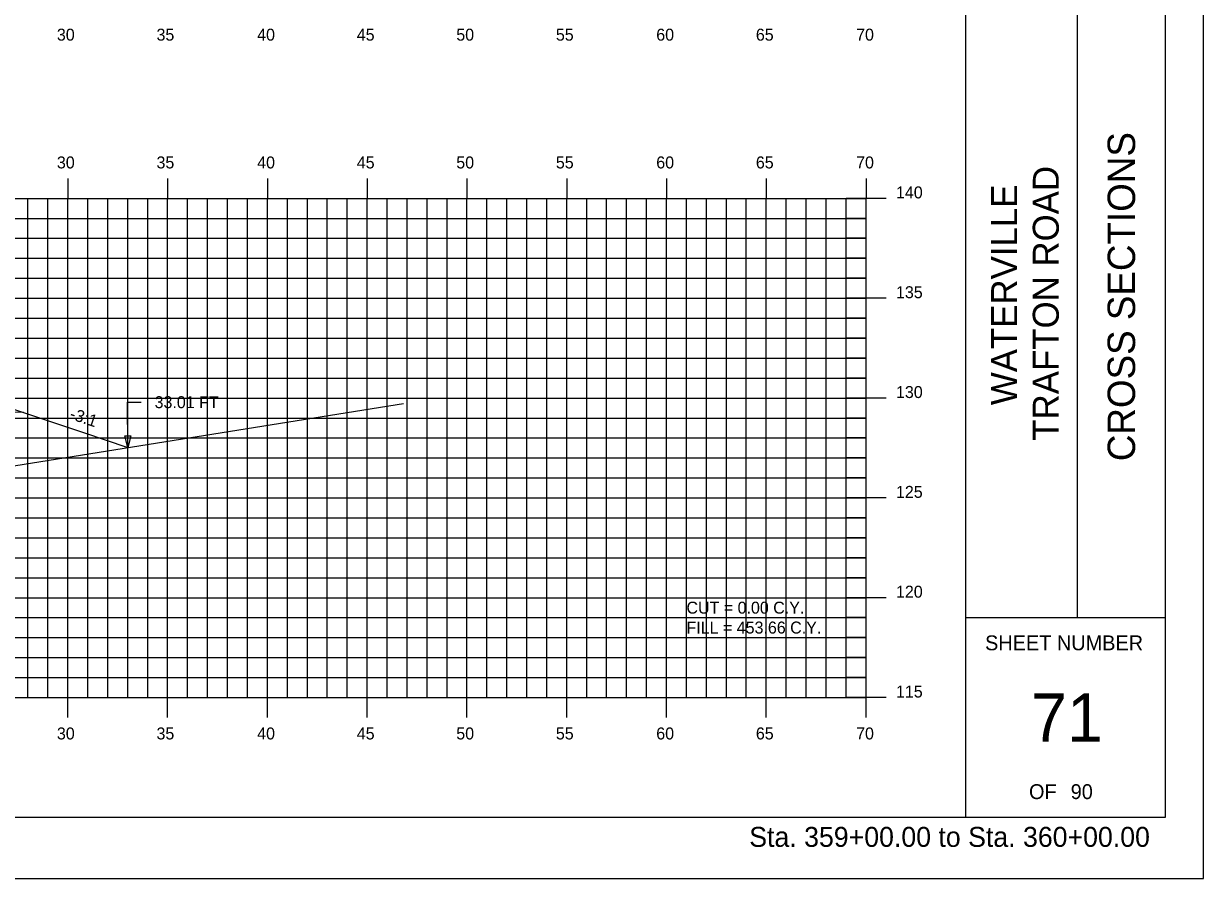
# Model space of a CAD drawing. Extents: x 1146303 to 1146473, y 608981 to 609091.
# Drawn here: x 1146413.7 to 1146472.8, y 608981.3 to 609024.1 of the extents above; entities that cross this region are included whole.
import ezdxf

# ---------------------------------------------------------------- set-up
doc = ezdxf.new("R2010")
doc.units = 0
for name, color, linetype in [('ANNOTATION', 7, 'Continuous'), ('BORDER', 7, 'Continuous'), ('D_Roadway_SlopeLines', 7, 'Continuous'), ('D_Roadway_SubGrade', 7, 'Continuous'), ('D_Text_Standard', 7, 'Continuous'), ('H_V ANNOTATION', 7, 'Continuous'), ('HIGHWAY_TITLE', 7, 'Continuous'), ('MAJOR', 7, 'Continuous'), ('MINOR', 7, 'Continuous'), ('PLOT BOUNDARY', 7, 'Continuous'), ('S_Roadway_Centerline', 7, 'Continuous')]:
    doc.layers.add(name, color=color, linetype=linetype)

msp = doc.modelspace()

# ---------------------------------------------------------------- linework, layer by layer
msp.add_lwpolyline([(1146341.288, 608998.284), (1146357.382, 609003.649), (1146360.382, 609004.649), (1146367.914, 609007.159), (1146367.915, 609007.159), (1146374.915, 609007.439), (1146385.915, 609007.659), (1146396.915, 609007.439), (1146406.316, 609007.063), (1146413.695, 609004.604), (1146416.695, 609003.604), (1146418.924, 609002.861)])
at = {"layer": 'BORDER'}
for p, q in [((1146460.915, 608984.335), (1146460.915, 609089.335)), ((1146466.506, 608994.338), (1146466.506, 609029.338)), ((1146460.915, 608994.338), (1146470.915, 608994.338))]:
    msp.add_line(p, q, dxfattribs=at)
msp.add_lwpolyline([(1146310.915, 608984.335), (1146470.915, 608984.335), (1146470.915, 609089.335), (1146310.915, 609089.335)], close=True, dxfattribs=at)
at = {"layer": 'D_Roadway_SlopeLines'}
for points in [[(1146413.695, 609004.604), (1146416.695, 609003.604)], [(1146416.695, 609003.604), (1146418.924, 609002.861)]]:
    msp.add_lwpolyline(points, dxfattribs=at)
at = {"layer": 'D_Roadway_SubGrade'}
msp.add_lwpolyline([(1146396.915, 609007.023), (1146396.915, 609007.189), (1146406.316, 609006.813), (1146406.316, 609007.063), (1146406.316, 609007.063), (1146413.695, 609004.604), (1146396.915, 609004.939)], close=True, dxfattribs=at)
at = {"layer": 'D_Text_Standard'}
msp.add_lwpolyline([(1146418.924, 609002.861), (1146418.9, 609005.128), (1146419.58, 609005.128)], dxfattribs=at)
msp.add_lwpolyline([(1146418.924, 609002.861), (1146418.772, 609003.441), (1146419.063, 609003.444)], close=True, dxfattribs=at)
at = {"layer": 'MAJOR'}
for p, q in [((1146415.915, 609016.337), (1146415.915, 609015.335)), ((1146420.915, 609016.337), (1146420.915, 609015.335)), ((1146425.915, 609016.337), (1146425.915, 609015.335)), ((1146430.915, 609016.337), (1146430.915, 609015.335)), ((1146435.915, 609016.337), (1146435.915, 609015.335)), ((1146440.915, 609016.337), (1146440.915, 609015.335)), ((1146445.915, 609016.337), (1146445.915, 609015.335)), ((1146450.915, 609016.337), (1146450.915, 609015.335)), ((1146455.915, 609016.337), (1146455.915, 609015.335)), ((1146315.915, 609015.335), (1146455.915, 609015.335)), ((1146315.915, 609015.335), (1146455.915, 609015.335)), ((1146415.915, 608990.335), (1146415.915, 609015.335)), ((1146420.915, 608990.335), (1146420.915, 609015.335)), ((1146425.915, 608990.335), (1146425.915, 609015.335)), ((1146430.915, 608990.335), (1146430.915, 609015.335)), ((1146435.915, 608990.335), (1146435.915, 609015.335)), ((1146440.915, 608990.335), (1146440.915, 609015.335)), ((1146445.915, 608990.335), (1146445.915, 609015.335)), ((1146450.915, 608990.335), (1146450.915, 609015.335)), ((1146456.917, 609015.335), (1146454.913, 609015.335)), ((1146455.915, 608990.335), (1146455.915, 609015.335)), ((1146455.915, 608990.335), (1146455.915, 609015.335)), ((1146315.915, 609010.335), (1146455.915, 609010.335)), ((1146456.917, 609010.335), (1146454.913, 609010.335)), ((1146315.915, 609005.335), (1146455.915, 609005.335)), ((1146456.917, 609005.335), (1146454.913, 609005.335)), ((1146315.915, 609000.335), (1146455.915, 609000.335)), ((1146456.917, 609000.335), (1146454.913, 609000.335)), ((1146315.915, 608995.335), (1146455.915, 608995.335)), ((1146456.917, 608995.335), (1146454.913, 608995.335)), ((1146315.915, 608990.335), (1146455.915, 608990.335)), ((1146315.915, 608990.335), (1146455.915, 608990.335)), ((1146415.915, 608989.333), (1146415.915, 608990.335)), ((1146420.915, 608989.333), (1146420.915, 608990.335)), ((1146425.915, 608989.333), (1146425.915, 608990.335)), ((1146430.915, 608989.333), (1146430.915, 608990.335)), ((1146435.915, 608989.333), (1146435.915, 608990.335)), ((1146440.915, 608989.333), (1146440.915, 608990.335)), ((1146445.915, 608989.333), (1146445.915, 608990.335)), ((1146450.915, 608989.333), (1146450.915, 608990.335)), ((1146456.917, 608990.335), (1146454.913, 608990.335)), ((1146455.915, 608989.333), (1146455.915, 608990.335))]:
    msp.add_line(p, q, dxfattribs=at)
at = {"layer": 'MINOR'}
for p, q in [((1146413.915, 608990.335), (1146413.915, 609015.335)), ((1146414.915, 608990.335), (1146414.915, 609015.335)), ((1146416.915, 608990.335), (1146416.915, 609015.335)), ((1146417.915, 608990.335), (1146417.915, 609015.335)), ((1146418.915, 608990.335), (1146418.915, 609015.335)), ((1146419.915, 608990.335), (1146419.915, 609015.335)), ((1146421.915, 608990.335), (1146421.915, 609015.335)), ((1146422.915, 608990.335), (1146422.915, 609015.335)), ((1146423.915, 608990.335), (1146423.915, 609015.335)), ((1146424.915, 608990.335), (1146424.915, 609015.335)), ((1146426.915, 608990.335), (1146426.915, 609015.335)), ((1146427.915, 608990.335), (1146427.915, 609015.335)), ((1146428.915, 608990.335), (1146428.915, 609015.335)), ((1146429.915, 608990.335), (1146429.915, 609015.335)), ((1146431.915, 608990.335), (1146431.915, 609015.335)), ((1146432.915, 608990.335), (1146432.915, 609015.335)), ((1146433.915, 608990.335), (1146433.915, 609015.335)), ((1146434.915, 608990.335), (1146434.915, 609015.335)), ((1146436.915, 608990.335), (1146436.915, 609015.335)), ((1146437.915, 608990.335), (1146437.915, 609015.335)), ((1146438.915, 608990.335), (1146438.915, 609015.335)), ((1146439.915, 608990.335), (1146439.915, 609015.335)), ((1146441.915, 608990.335), (1146441.915, 609015.335)), ((1146442.915, 608990.335), (1146442.915, 609015.335)), ((1146443.915, 608990.335), (1146443.915, 609015.335)), ((1146444.915, 608990.335), (1146444.915, 609015.335)), ((1146446.915, 608990.335), (1146446.915, 609015.335)), ((1146447.915, 608990.335), (1146447.915, 609015.335)), ((1146448.915, 608990.335), (1146448.915, 609015.335)), ((1146449.915, 608990.335), (1146449.915, 609015.335)), ((1146451.915, 608990.335), (1146451.915, 609015.335)), ((1146452.915, 608990.335), (1146452.915, 609015.335)), ((1146453.915, 608990.335), (1146453.915, 609015.335)), ((1146454.915, 608990.335), (1146454.915, 609015.335)), ((1146315.915, 609014.335), (1146455.915, 609014.335)), ((1146455.915, 609014.335), (1146454.913, 609014.335)), ((1146315.915, 609013.335), (1146455.915, 609013.335)), ((1146455.915, 609013.335), (1146454.913, 609013.335)), ((1146315.915, 609012.335), (1146455.915, 609012.335)), ((1146455.915, 609012.335), (1146454.913, 609012.335)), ((1146315.915, 609011.335), (1146455.915, 609011.335)), ((1146455.915, 609011.335), (1146454.913, 609011.335)), ((1146315.915, 609009.335), (1146455.915, 609009.335)), ((1146455.915, 609009.335), (1146454.913, 609009.335)), ((1146315.915, 609008.335), (1146455.915, 609008.335)), ((1146455.915, 609008.335), (1146454.913, 609008.335)), ((1146315.915, 609007.335), (1146455.915, 609007.335)), ((1146455.915, 609007.335), (1146454.913, 609007.335)), ((1146315.915, 609006.335), (1146455.915, 609006.335)), ((1146455.915, 609006.335), (1146454.913, 609006.335)), ((1146315.915, 609004.335), (1146455.915, 609004.335)), ((1146455.915, 609004.335), (1146454.913, 609004.335)), ((1146315.915, 609003.335), (1146455.915, 609003.335)), ((1146455.915, 609003.335), (1146454.913, 609003.335)), ((1146315.915, 609002.335), (1146455.915, 609002.335)), ((1146455.915, 609002.335), (1146454.913, 609002.335)), ((1146315.915, 609001.335), (1146455.915, 609001.335)), ((1146455.915, 609001.335), (1146454.913, 609001.335)), ((1146315.915, 608999.335), (1146455.915, 608999.335)), ((1146455.915, 608999.335), (1146454.913, 608999.335)), ((1146315.915, 608998.335), (1146455.915, 608998.335)), ((1146455.915, 608998.335), (1146454.913, 608998.335)), ((1146315.915, 608997.335), (1146455.915, 608997.335)), ((1146455.915, 608997.335), (1146454.913, 608997.335)), ((1146315.915, 608996.335), (1146455.915, 608996.335)), ((1146455.915, 608996.335), (1146454.913, 608996.335)), ((1146315.915, 608994.335), (1146455.915, 608994.335)), ((1146455.915, 608994.335), (1146454.913, 608994.335)), ((1146315.915, 608993.335), (1146455.915, 608993.335)), ((1146455.915, 608993.335), (1146454.913, 608993.335)), ((1146315.915, 608992.335), (1146455.915, 608992.335)), ((1146455.915, 608992.335), (1146454.913, 608992.335)), ((1146315.915, 608991.335), (1146455.915, 608991.335)), ((1146455.915, 608991.335), (1146454.913, 608991.335))]:
    msp.add_line(p, q, dxfattribs=at)
at = {"layer": 'PLOT BOUNDARY'}
msp.add_lwpolyline([(1146302.822, 608981.276), (1146472.822, 608981.276), (1146472.822, 609091.276), (1146302.822, 609091.276)], close=True, dxfattribs=at)
at = {"layer": 'S_Roadway_Centerline'}
msp.add_lwpolyline([(1146333.102, 608997.996), (1146337.13, 608998.116), (1146349.153, 608998.601), (1146351.613, 608998.852), (1146359.482, 608999.63), (1146363.256, 609000.633), (1146368.628, 609001.831), (1146370.301, 609001.988), (1146372.447, 609002.232), (1146378.334, 609002.421), (1146383.797, 609002.585), (1146389.233, 609002.425), (1146394.809, 609002.215), (1146396.683, 609001.977), (1146398.464, 609001.775), (1146403.062, 608998.9), (1146403.617, 608998.566), (1146408.502, 609000.653), (1146410.677, 609001.551), (1146412.036, 609001.76), (1146432.73, 609005.067)], dxfattribs=at)

# ---------------------------------------------------------------- texts
at = {"layer": 'ANNOTATION'}
msp.add_text('-3:1', height=0.6, rotation=341.56505, dxfattribs=at).set_placement((1146415.959, 609004.303))
at = {"layer": 'BORDER'}
msp.add_text('CROSS SECTIONS', height=1.37787, rotation=90, dxfattribs=at).set_placement((1146469.399, 609002.172))
for s, height, p in [('SHEET NUMBER', 0.74527, (1146461.88, 608992.701)), ('71', 2.4194, (1146464.186, 608988.118)), ('OF', 0.7453, (1146464.082, 608985.248)), ('90', 0.7453, (1146466.171, 608985.248))]:
    msp.add_text(s, height=height, dxfattribs=at).set_placement(p)
at = {"layer": 'D_Text_Standard'}
for s, p in [('33.01 FT', (1146420.26, 609004.828)), ('CUT = 0.00 C.Y.', (1146446.915, 608994.535)), ('FILL = 453.66 C.Y.', (1146446.915, 608993.539))]:
    msp.add_text(s, height=0.6, dxfattribs=at).set_placement(p)
at = {"layer": 'H_V ANNOTATION'}
for s, height, p in [('30', 0.6, (1146415.363, 609023.235)), ('35', 0.6, (1146420.355, 609023.235)), ('40', 0.6, (1146425.401, 609023.235)), ('45', 0.6, (1146430.393, 609023.235)), ('50', 0.6, (1146435.379, 609023.235)), ('55', 0.6, (1146440.371, 609023.235)), ('60', 0.6, (1146445.401, 609023.235)), ('65', 0.6, (1146450.393, 609023.235)), ('70', 0.6, (1146455.417, 609023.235)), ('30', 0.6, (1146415.363, 609016.835)), ('35', 0.6, (1146420.355, 609016.835)), ('40', 0.6, (1146425.401, 609016.835)), ('45', 0.6, (1146430.393, 609016.835)), ('50', 0.6, (1146435.379, 609016.835)), ('55', 0.6, (1146440.371, 609016.835)), ('60', 0.6, (1146445.401, 609016.835)), ('65', 0.6, (1146450.393, 609016.835)), ('70', 0.6, (1146455.417, 609016.835)), ('140', 0.6, (1146457.415, 609015.335)), ('135', 0.6, (1146457.415, 609010.335)), ('130', 0.6, (1146457.415, 609005.335)), ('125', 0.6, (1146457.415, 609000.335)), ('120', 0.6, (1146457.415, 608995.335)), ('115', 0.6, (1146457.415, 608990.335)), ('30', 0.6, (1146415.363, 608988.235)), ('35', 0.6, (1146420.355, 608988.235)), ('40', 0.6, (1146425.401, 608988.235)), ('45', 0.6, (1146430.393, 608988.235)), ('50', 0.6, (1146435.379, 608988.235)), ('55', 0.6, (1146440.371, 608988.235)), ('60', 0.6, (1146445.401, 608988.235)), ('65', 0.6, (1146450.393, 608988.235)), ('70', 0.6, (1146455.417, 608988.235)), ('Sta. 359+00.00 to Sta. 360+00.00', 1.0002, (1146450.061, 608982.855))]:
    msp.add_text(s, height=height, dxfattribs=at).set_placement(p)
at = {"layer": 'HIGHWAY_TITLE'}
for s, height, p in [('TRAFTON ROAD', 1.30428, (1146465.574, 609003.201)), ('WATERVILLE', 1.3043, (1146463.487, 609004.98))]:
    msp.add_text(s, height=height, rotation=90, dxfattribs=at).set_placement(p)

doc.saveas('drawing.dxf')
